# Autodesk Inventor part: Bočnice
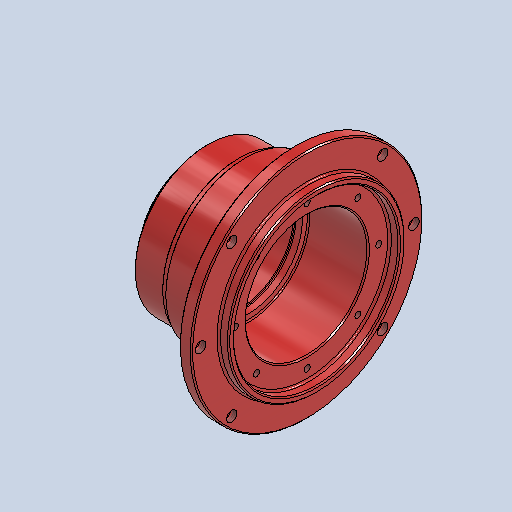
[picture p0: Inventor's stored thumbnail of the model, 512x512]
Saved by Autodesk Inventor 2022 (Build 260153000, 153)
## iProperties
Created: 2025-05
Part Number: Bočnice
Material: Všeobecné
Document SubType Name: Modeling
Designer: jbart
Density: 1 g/cm^3
Appearance: Oranžovo-červená
Mass: 5576.32 g
Surface Area: 4782.11 cm^2
Volume: 5576.32 cm^3
Author: jbart
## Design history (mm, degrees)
sketch "Náčrt1"
  geometry: L1 (0, 0)-(200, 0); L2 (200, 135)-(200, 145); L3 (200, 145)-(184, 145); L4 (184, 145)-(184, 190); L5 (0, 93)-(20, 93); L6 (20, 93)-(20, 120); L7 (20, 120)-(71, 120); L8 (71, 120)-(71, 125); L9 (71, 125)-(81, 125); L10 (81, 125)-(81, 130); L11 (81, 130)-(144.5, 130); L12 (144.5, 130)-(144.5, 160); L13 (144.5, 160)-(164, 160); L14 (164, 160)-(164, 190); L15 (164, 190)-(184, 190); L16 (30, 90)-(30, 77); L17 (30, 77)-(0, 77); L18 (0, 93)-(0, 77); L19 (30, 90)-(72, 90); L20 (72, 90)-(72, 92.5); L21 (72, 92.5)-(76.15, 92.5); L22 (76.15, 92.5)-(76.15, 90); L23 (76.15, 90)-(86.15, 90); L24 (86.15, 90)-(86.15, 100); L25 (86.15, 100)-(184, 100); L26 (200, 135)-(184, 135); L27 (184, 135)-(184, 100); 4 further points
  constraints: 54 end point, 16 perpendicular, 5 horizontal, 4 midpoint, 3 vertical, 3 vertical alignment, 1 parallel, 1 point on line
  dimensions: "d0" = 200 distance of L1.start L1.end; "d6" = 186 diameter of L5 L1; "d7" = 240 diameter of L7 L1; "d8" = 51 distance of L6.end L7.end; "d9" = 20 distance of L5.start L5.end; "d10" = 260 diameter of L11 L1; "d11" = 63.5 distance of L10.end L11.end; "d12" = 10 distance of L8.end L9.end; "d13" = 250 diameter of L9 L1; "d36" = 42 distance of L16.start L19.end; "d37" = 4.15 distance of L20.end L21.end; "d38" = 185 diameter of L21 L1; "d39" = 10 distance of L22.end L23.end; "d40" = 180 diameter of L19 L1; "d41" = 30 distance of L16.end L17.end; "d42" = 154 diameter of L17 L1; "d43" = 200 diameter of L25 L1; "d44" = 270 diameter of L26 L1; "d46" = 290 diameter of L3 L1; "d57" = 16 distance of L2.start L26.end; "d61" = 380 diameter of L15 L1; "d87" = 20 distance of L14.end L4.end; "d88" = 320 diameter of L13 L1
revolve "Rotace1" sketch "Náčrt1" stored, may be unused: angle "d18" = 90 deg
sketch "Náčrt2" dims "d19" = 170
  geometry: L1 (0, 0)-(0, 110.5); L2 (0, 0)-(-73.612, 42.5); 3 further points
  constraints: 4 end point, 2 coincident, 1 vertical, 3 other
  dimensions: "d20" = 60 deg angle of L1 L2
hole "Díra2" sketch "Náčrt2" at (-73.612, 42.5) diameter "d47" = 10.106; stored, may be unused: countersink angle "d51" = 90 deg, drill point angle "d53" = 118 deg; dims "d48" = 20, "d49" = 4, "d50" = 2, "d52" = 25
pattern_circular "Kruhové pole2" dims angle "d55" = 360 deg
sketch "Náčrt5" dims "d62" = 235
  geometry: L1 (0, 0)-(0, 117.5); 2 further points
  constraints: 2 coincident, 2 end point, 1 vertical, 1 vertical alignment, 2 other
hole "Díra3" sketch "Náčrt5" at (0, 117.5) diameter "d63" = 10.106; stored, may be unused: countersink angle "d67" = 90 deg, drill point angle "d69" = 118 deg; dims "d64" = 15, "d65" = 4, "d66" = 2, "d68" = 20
pattern_circular "Kruhové pole3" dims angle "d71" = 360 deg
chamfer "Zkosení1" distance "d73" = 2; stored, may be unused: second distance "d74" = 2, angle "d75" = 45 deg
fillet "Zaoblení1" dims "d76" = 3
chamfer "Zkosení2" distance "d77" = 2; stored, may be unused: second distance "d78" = 2, angle "d79" = 45 deg
chamfer "Zkosení3" distance "d80" = 1; stored, may be unused: second distance "d81" = 2, angle "d82" = 45 deg
fillet "Zaoblení2" dims "d83" = 1
chamfer "Zkosení4" distance "d84" = 2; stored, may be unused: second distance "d85" = 2, angle "d86" = 45 deg
sketch "Náčrt6"
  geometry: L1 (0, 0)-(-175, 0); L2 (0, 0)-(-123.744, 123.744); L3 (0, 0)-(-123.744, -123.744); A1 r 175 centre (0, 0) between (-175, 0) and (-123.744, 123.744); 4 further points
  constraints: 6 end point, 4 coincident, 3 point on circle, 1 centre point, 1 horizontal
  dimensions: "d89" = 350 diameter of A1; "d97" = 45 deg angle of L1 L2; "d98" = 90 deg angle of L2 L3
hole "Díra5" sketch "Náčrt6" at (-175, 0), (-123.744, 123.744), (-123.744, -123.744) diameter "d99" = 17.294; stored, may be unused: countersink angle "d103" = 90 deg, drill point angle "d105" = 118 deg; dims "d100" = 8, "d101" = 4, "d102" = 2, "d104" = 10
mirror "Zrcadlit2"
fillet "Zaoblení3" dims "d106" = 2
fillet "Zaoblení4" dims "d107" = 5
node "Těleso1"
